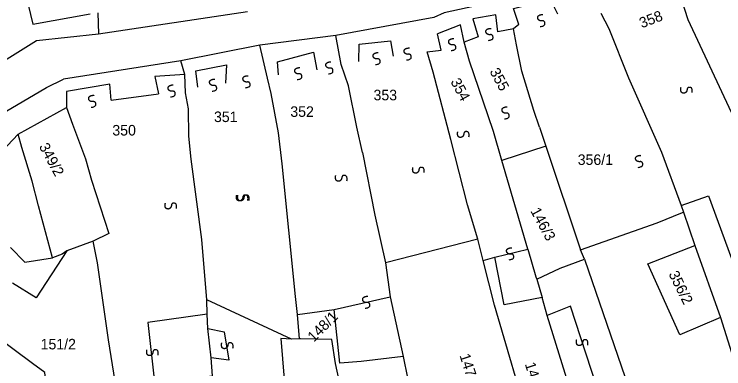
# Model space of a CAD drawing. Extents: x -581999 to -572728, y -1219553 to -1212032.
# Drawn here: x -577714.8 to -577580.3, y -1215727.3 to -1215660.1 of the extents above; entities that cross this region are included whole.
import ezdxf

# ---------------------------------------------------------------- set-up
doc = ezdxf.new("R2010")
doc.units = 0
for name, color, linetype in [('Vrstva 1', 7, 'Continuous'), ('Vrstva 2', 7, 'Continuous'), ('Vrstva 4', 7, 'Continuous'), ('Vrstva 6', 7, 'Continuous')]:
    doc.layers.add(name, color=color, linetype=linetype)

msp = doc.modelspace()

# ---------------------------------------------------------------- linework, layer by layer
at = {"layer": 'Vrstva 1'}
msp.add_line((-577682.456, -1215671.509), (-577683.252, -1215668.949), dxfattribs=at)
for points in [[(-577702.715, -1215611.05), (-577707.55, -1215614.997), (-577714.464, -1215648.832), (-577711.301, -1215661.986), (-577700.407, -1215660.043)], [(-577613.694, -1215654.996), (-577622.577, -1215657.523), (-577633.304, -1215659.812), (-577635.267, -1215660.737)], [(-577619.14, -1215662.069), (-577620.164, -1215659.043), (-577613.242, -1215657.206), (-577611.814, -1215660.001)], [(-577588.315, -1215657.32), (-577587.122, -1215661.102)], [(-577698.978, -1215659.866), (-577698.815, -1215663.828)], [(-577698.815, -1215663.828), (-577670.605, -1215659.602)], [(-577623.179, -1215663.45), (-577623.51, -1215660.194), (-577627.893, -1215660.993), (-577626.87, -1215664.369)], [(-577603.632, -1215659.936), (-577602.104, -1215662.83)], [(-577635.267, -1215660.737), (-577653.837, -1215664.163)], [(-577587.122, -1215661.102), (-577578.944, -1215678.684)], [(-577629.525, -1215665.406), (-577630.202, -1215662.148), (-577634.588, -1215663.82)], [(-577620.181, -1215662.879), (-577623.179, -1215663.45)], [(-577619.14, -1215662.069), (-577620.181, -1215662.879)], [(-577619.618, -1215665.903), (-577620.181, -1215662.879)], [(-577602.104, -1215662.83), (-577598.401, -1215672.177)], [(-577735.744, -1215682.066), (-577719.727, -1215670.767), (-577710.564, -1215665.069), (-577698.815, -1215663.828)], [(-577653.837, -1215664.163), (-577668.253, -1215665.975)], [(-577652.823, -1215669.63), (-577653.837, -1215664.163)], [(-577633.91, -1215666.902), (-577634.588, -1215663.82)], [(-577626.87, -1215664.369), (-577629.525, -1215665.406)], [(-577628.503, -1215669.013), (-577629.525, -1215665.406)], [(-577668.253, -1215665.975), (-577683.252, -1215668.949)], [(-577666.78, -1215672.259), (-577668.253, -1215665.975)], [(-577636.562, -1215667.242), (-577633.91, -1215666.902)], [(-577616.33, -1215678.352), (-577618.617, -1215670.901), (-577619.618, -1215665.903)], [(-577635.426, -1215671.083), (-577636.562, -1215667.242)], [(-577683.252, -1215668.949), (-577705.448, -1215672.439)], [(-577651.456, -1215673.704), (-577652.823, -1215669.63)], [(-577624.975, -1215679.37), (-577628.503, -1215669.013)], [(-577682.456, -1215671.509), (-577688.15, -1215671.915), (-577687.471, -1215675.173)], [(-577682.354, -1215674.998), (-577682.456, -1215671.509)], [(-577666.101, -1215675.167), (-577666.78, -1215672.259)], [(-577632.068, -1215683.842), (-577635.426, -1215671.083)], [(-577598.401, -1215672.177), (-577592.109, -1215686.233), (-577588.384, -1215696.39)], [(-577708.727, -1215673.992), (-577705.448, -1215672.439)], [(-577696.469, -1215676.423), (-577696.688, -1215673.398), (-577704.88, -1215674.767), (-577704.911, -1215677.765)], [(-577649.875, -1215681.498), (-577651.456, -1215673.704)], [(-577914.873, -1215726.747), (-577886.58, -1215723.734), (-577884.746, -1215723.515), (-577875.236, -1215722.423), (-577874.505, -1215722.12), (-577863.622, -1215720.85), (-577862.999, -1215720.979), (-577844.985, -1215718.754), (-577796.098, -1215711.415), (-577783.814, -1215709.901), (-577749.511, -1215702.562), (-577738.438, -1215696.009), (-577724.392, -1215683.952), (-577717.64, -1215679.235), (-577708.727, -1215673.992)], [(-577681.79, -1215678.023), (-577682.354, -1215674.998)], [(-577696.469, -1215676.423), (-577687.471, -1215675.173)], [(-577664.747, -1215682.612), (-577666.101, -1215675.167)], [(-577714.064, -1215682.842), (-577704.911, -1215677.765)], [(-577704.911, -1215677.765), (-577703.747, -1215680.96)], [(-577681.695, -1215683.255), (-577681.79, -1215678.023)], [(-577615.266, -1215681.526), (-577616.33, -1215678.352)], [(-577623.944, -1215682.319), (-577624.975, -1215679.37)], [(-577703.747, -1215680.96), (-577701.33, -1215687.533)], [(-577648.777, -1215686.329), (-577649.875, -1215681.498)], [(-577615.266, -1215681.526), (-577614.055, -1215685.1)], [(-577714.064, -1215682.842), (-577722.147, -1215691.388), (-577724.874, -1215694.936)], [(-577713.351, -1215685.398), (-577714.064, -1215682.842)], [(-577664.041, -1215688.467), (-577664.747, -1215682.612)], [(-577622.362, -1215687.863), (-577623.944, -1215682.319)], [(-577681.299, -1215687.604), (-577681.695, -1215683.255)], [(-577628.867, -1215696.25), (-577632.068, -1215683.842)], [(-577711.386, -1215691.788), (-577713.351, -1215685.398)], [(-577614.055, -1215685.1), (-577622.362, -1215687.863)], [(-577614.055, -1215685.1), (-577607.507, -1215704.793)], [(-577648.777, -1215686.329), (-577646.477, -1215698.187)], [(-577701.33, -1215687.533), (-577700.171, -1215691.55)], [(-577679.283, -1215702.801), (-577681.299, -1215687.604)], [(-577661.522, -1215713.635), (-577664.041, -1215688.467)], [(-577617.445, -1215704.636), (-577622.362, -1215687.863)], [(-577710.228, -1215696.442), (-577711.386, -1215691.788)], [(-577700.171, -1215691.55), (-577696.865, -1215701.681), (-577699.854, -1215703.131)], [(-577588.384, -1215696.39), (-577583.201, -1215694.517)], [(-577583.201, -1215694.517), (-577572.653, -1215723.27)], [(-577707.553, -1215706.298), (-577710.228, -1215696.442)], [(-577626.921, -1215702.783), (-577628.867, -1215696.25)], [(-577588.384, -1215696.39), (-577587.93, -1215697.611)], [(-577592.941, -1215699.643), (-577588.119, -1215697.693), (-577587.93, -1215697.611)], [(-577587.93, -1215697.611), (-577585.804, -1215703.949)], [(-577646.477, -1215698.187), (-577644.436, -1215707.218)], [(-577607.507, -1215704.793), (-577592.941, -1215699.643)], [(-577699.854, -1215703.131), (-577704.835, -1215704.939)], [(-577693.061, -1215745.931), (-577696.944, -1215721.858), (-577699.052, -1215707.217), (-577699.854, -1215703.131)], [(-577678.335, -1215714.289), (-577679.283, -1215702.801)], [(-577626.921, -1215702.783), (-577644.436, -1215707.218)], [(-577625.945, -1215706.796), (-577626.921, -1215702.783)], [(-577715.504, -1215704.359), (-577712.801, -1215707.103), (-577707.553, -1215706.298)], [(-577617.445, -1215704.636), (-577615.932, -1215709.927), (-577615.759, -1215710.366)], [(-577580.965, -1215717.624), (-577588.68, -1215720.898), (-577594.688, -1215707.455), (-577585.804, -1215703.949)], [(-577585.804, -1215703.949), (-577580.965, -1215717.624)], [(-577704.835, -1215704.939), (-577710.656, -1215713.856), (-577715.168, -1215711.106)], [(-577704.835, -1215704.939), (-577705.741, -1215705.574), (-577707.553, -1215706.298)], [(-577606.708, -1215706.567), (-577607.507, -1215704.793)], [(-577644.436, -1215707.218), (-577643.56, -1215713.691)], [(-577625.945, -1215706.796), (-577623.686, -1215706.166)], [(-577616.887, -1215738.765), (-577623.812, -1215715.278), (-577625.945, -1215706.796)], [(-577614.775, -1215713.849), (-577621.917, -1215715.194), (-577623.686, -1215706.166)], [(-577615.759, -1215710.366), (-577611.324, -1215708.284), (-577606.708, -1215706.567)], [(-577606.708, -1215706.567), (-577599.039, -1215729.005)], [(-577615.759, -1215710.366), (-577614.775, -1215713.849)], [(-577661.091, -1215717.068), (-577661.522, -1215713.635)], [(-577643.56, -1215713.691), (-577641.076, -1215724.999)], [(-577613.801, -1215717.207), (-577614.775, -1215713.849)], [(-577678.212, -1215717.002), (-577678.335, -1215714.289)], [(-577662.285, -1215721.712), (-577678.335, -1215714.289)], [(-577661.091, -1215717.068), (-577654.164, -1215716.124)], [(-577653.079, -1215726.283), (-577654.164, -1215716.124)], [(-577678.09, -1215719.715), (-577678.212, -1215717.002)], [(-577660.748, -1215721.626), (-577661.091, -1215717.068)], [(-577607.744, -1215736.632), (-577609.259, -1215731.89), (-577613.801, -1215717.207)], [(-577580.965, -1215717.624), (-577574.064, -1215739.543)], [(-577711.336, -1215726.312), (-577721.347, -1215718.929)], [(-577677.479, -1215725.277), (-577678.09, -1215719.715)], [(-577662.285, -1215721.712), (-577664.284, -1215721.582), (-577662.648, -1215741.635)], [(-577660.748, -1215721.626), (-577662.285, -1215721.712)], [(-577653.297, -1215729.272), (-577653.909, -1215726.352), (-577654.614, -1215721.793), (-577660.578, -1215721.683), (-577660.748, -1215721.626)], [(-577677.221, -1215728.649), (-577677.479, -1215725.277)], [(-577641.076, -1215724.999), (-577649.031, -1215725.94), (-577653.079, -1215726.283)], [(-577641.076, -1215724.999), (-577640.284, -1215729.038)], [(-577708.642, -1215731.424), (-577708.992, -1215728.051), (-577711.336, -1215726.312)]]:
    msp.add_lwpolyline(points, dxfattribs=at)
at = {"layer": 'Vrstva 4'}
for p, q in [((-577609.361, -1215715.461), (-577613.801, -1215717.207)), ((-577604.345, -1215730.793), (-577609.361, -1215715.461))]:
    msp.add_line(p, q, dxfattribs=at)
for points in [[(-577649.477, -1215669.061), (-577649.464, -1215665.805), (-577643.468, -1215665.127), (-577643.019, -1215668.035)], [(-577664.702, -1215671.568), (-577664.923, -1215669.125), (-577658.115, -1215667.288), (-577657.437, -1215670.661)], [(-577680.044, -1215673.959), (-577680.377, -1215670.819), (-577674.609, -1215669.675), (-577674.737, -1215673.163)], [(-577623.686, -1215706.166), (-577617.445, -1215704.636)], [(-577654.164, -1215716.124), (-577643.56, -1215713.691)], [(-577678.212, -1215717.002), (-577689.475, -1215718.553), (-577688.254, -1215729.86), (-577677.221, -1215728.649)], [(-577678.09, -1215719.715), (-577675.024, -1215720.306), (-577674.142, -1215725.687), (-577677.479, -1215725.277)]]:
    msp.add_lwpolyline(points, dxfattribs=at)
at = {"layer": 'Vrstva 6'}
for points in [[(-577615.117, -1215662.436), (-577614.266, -1215662.347), (-577614.214, -1215661.589), (-577614.53, -1215661.333), (-577614.946, -1215661.378), (-577615.278, -1215661.296), (-577615.495, -1215661.088), (-577615.586, -1215660.876), (-577615.587, -1215660.607), (-577615.384, -1215660.302), (-577614.796, -1215660.132), (-577614.616, -1215660.165)], [(-577624.938, -1215665.063), (-577624.087, -1215664.974), (-577624.035, -1215664.216), (-577624.351, -1215663.96), (-577624.767, -1215664.005), (-577625.099, -1215663.923), (-577625.316, -1215663.715), (-577625.407, -1215663.503), (-577625.408, -1215663.234), (-577625.205, -1215662.929), (-577624.617, -1215662.759), (-577624.437, -1215662.792)], [(-577631.998, -1215667.002), (-577631.147, -1215666.913), (-577631.095, -1215666.155), (-577631.411, -1215665.899), (-577631.827, -1215665.944), (-577632.159, -1215665.862), (-577632.376, -1215665.654), (-577632.467, -1215665.442), (-577632.468, -1215665.173), (-577632.265, -1215664.868), (-577631.677, -1215664.698), (-577631.497, -1215664.731)], [(-577640.433, -1215668.785), (-577639.582, -1215668.696), (-577639.53, -1215667.938), (-577639.846, -1215667.682), (-577640.262, -1215667.727), (-577640.594, -1215667.645), (-577640.811, -1215667.437), (-577640.902, -1215667.225), (-577640.903, -1215666.956), (-577640.7, -1215666.651), (-577640.112, -1215666.481), (-577639.932, -1215666.514)], [(-577646.326, -1215669.66), (-577645.475, -1215669.571), (-577645.423, -1215668.813), (-577645.739, -1215668.557), (-577646.155, -1215668.602), (-577646.487, -1215668.52), (-577646.704, -1215668.312), (-577646.795, -1215668.1), (-577646.796, -1215667.831), (-577646.593, -1215667.526), (-577646.005, -1215667.356), (-577645.825, -1215667.389)], [(-577655.274, -1215671.411), (-577654.423, -1215671.322), (-577654.371, -1215670.564), (-577654.687, -1215670.308), (-577655.103, -1215670.353), (-577655.435, -1215670.271), (-577655.652, -1215670.063), (-577655.743, -1215669.851), (-577655.744, -1215669.582), (-577655.541, -1215669.277), (-577654.953, -1215669.107), (-577654.773, -1215669.14)], [(-577661.167, -1215672.506), (-577660.316, -1215672.417), (-577660.264, -1215671.659), (-577660.58, -1215671.403), (-577660.996, -1215671.448), (-577661.328, -1215671.366), (-577661.545, -1215671.158), (-577661.636, -1215670.946), (-577661.637, -1215670.677), (-577661.434, -1215670.372), (-577660.846, -1215670.202), (-577660.666, -1215670.235)], [(-577670.988, -1215674.038), (-577670.137, -1215673.949), (-577670.085, -1215673.191), (-577670.401, -1215672.935), (-577670.817, -1215672.98), (-577671.149, -1215672.898), (-577671.366, -1215672.69), (-577671.457, -1215672.478), (-577671.458, -1215672.209), (-577671.255, -1215671.904), (-577670.667, -1215671.734), (-577670.487, -1215671.767)], [(-577685.174, -1215675.789), (-577684.323, -1215675.7), (-577684.271, -1215674.942), (-577684.587, -1215674.686), (-577685.003, -1215674.731), (-577685.335, -1215674.649), (-577685.552, -1215674.441), (-577685.643, -1215674.229), (-577685.644, -1215673.96), (-577685.441, -1215673.655), (-577684.853, -1215673.485), (-577684.673, -1215673.518)], [(-577677.317, -1215674.695), (-577676.466, -1215674.606), (-577676.414, -1215673.848), (-577676.73, -1215673.592), (-577677.146, -1215673.637), (-577677.478, -1215673.555), (-577677.695, -1215673.347), (-577677.786, -1215673.135), (-577677.787, -1215672.866), (-577677.584, -1215672.561), (-577676.996, -1215672.391), (-577676.816, -1215672.424)], [(-577586.307, -1215674.972), (-577586.212, -1215674.121), (-577586.942, -1215673.909), (-577587.259, -1215674.163), (-577587.304, -1215674.579), (-577587.455, -1215674.886), (-577587.704, -1215675.053), (-577587.931, -1215675.097), (-577588.194, -1215675.041), (-577588.449, -1215674.777), (-577588.489, -1215674.167), (-577588.419, -1215673.998)], [(-577700.233, -1215677.759), (-577699.382, -1215677.67), (-577699.33, -1215676.912), (-577699.646, -1215676.656), (-577700.062, -1215676.701), (-577700.394, -1215676.619), (-577700.611, -1215676.411), (-577700.702, -1215676.199), (-577700.703, -1215675.93), (-577700.5, -1215675.625), (-577699.912, -1215675.455), (-577699.732, -1215675.488)], [(-577621.883, -1215679.948), (-577621.032, -1215679.859), (-577620.98, -1215679.101), (-577621.296, -1215678.845), (-577621.712, -1215678.89), (-577622.044, -1215678.808), (-577622.261, -1215678.6), (-577622.352, -1215678.388), (-577622.353, -1215678.119), (-577622.15, -1215677.814), (-577621.562, -1215677.644), (-577621.382, -1215677.677)], [(-577628.615, -1215683.357), (-577628.52, -1215682.506), (-577629.25, -1215682.294), (-577629.567, -1215682.548), (-577629.612, -1215682.964), (-577629.763, -1215683.271), (-577630.012, -1215683.438), (-577630.239, -1215683.482), (-577630.502, -1215683.426), (-577630.757, -1215683.162), (-577630.797, -1215682.552), (-577630.727, -1215682.383)], [(-577596.566, -1215689.142), (-577595.715, -1215689.053), (-577595.663, -1215688.295), (-577595.979, -1215688.039), (-577596.395, -1215688.084), (-577596.727, -1215688.002), (-577596.944, -1215687.794), (-577597.035, -1215687.582), (-577597.036, -1215687.313), (-577596.833, -1215687.008), (-577596.245, -1215686.838), (-577596.065, -1215686.871)], [(-577637.127, -1215690.143), (-577637.032, -1215689.292), (-577637.762, -1215689.08), (-577638.079, -1215689.334), (-577638.124, -1215689.75), (-577638.275, -1215690.057), (-577638.524, -1215690.224), (-577638.751, -1215690.268), (-577639.014, -1215690.212), (-577639.269, -1215689.948), (-577639.309, -1215689.338), (-577639.239, -1215689.169)], [(-577651.749, -1215691.675), (-577651.654, -1215690.824), (-577652.384, -1215690.612), (-577652.701, -1215690.866), (-577652.746, -1215691.282), (-577652.897, -1215691.589), (-577653.146, -1215691.756), (-577653.373, -1215691.8), (-577653.636, -1215691.744), (-577653.891, -1215691.48), (-577653.931, -1215690.87), (-577653.861, -1215690.701)], [(-577670.518, -1215695.397), (-577670.423, -1215694.546), (-577671.153, -1215694.334), (-577671.47, -1215694.588), (-577671.515, -1215695.004), (-577671.666, -1215695.311), (-577671.915, -1215695.478), (-577672.142, -1215695.522), (-577672.405, -1215695.466), (-577672.66, -1215695.202), (-577672.7, -1215694.592), (-577672.63, -1215694.423)], [(-577670.3, -1215695.397), (-577670.205, -1215694.546), (-577670.935, -1215694.334), (-577671.252, -1215694.588), (-577671.297, -1215695.004), (-577671.448, -1215695.311), (-577671.697, -1215695.478), (-577671.924, -1215695.522), (-577672.187, -1215695.466), (-577672.442, -1215695.202), (-577672.482, -1215694.592), (-577672.412, -1215694.423)], [(-577684.049, -1215696.929), (-577683.954, -1215696.078), (-577684.684, -1215695.866), (-577685.001, -1215696.12), (-577685.046, -1215696.536), (-577685.197, -1215696.843), (-577685.446, -1215697.01), (-577685.673, -1215697.054), (-577685.936, -1215696.998), (-577686.191, -1215696.734), (-577686.231, -1215696.124), (-577686.161, -1215695.955)], [(-577621.019, -1215706.668), (-577620.168, -1215706.579), (-577620.116, -1215705.821), (-577620.432, -1215705.565), (-577620.848, -1215705.61), (-577621.18, -1215705.528), (-577621.397, -1215705.32), (-577621.488, -1215705.108), (-577621.489, -1215704.839), (-577621.286, -1215704.534), (-577620.698, -1215704.364), (-577620.518, -1215704.397)], [(-577648.299, -1215715.862), (-577647.448, -1215715.773), (-577647.396, -1215715.015), (-577647.712, -1215714.759), (-577648.128, -1215714.804), (-577648.46, -1215714.722), (-577648.677, -1215714.514), (-577648.768, -1215714.302), (-577648.769, -1215714.033), (-577648.566, -1215713.728), (-577647.978, -1215713.558), (-577647.798, -1215713.591)], [(-577606.092, -1215722.832), (-577605.997, -1215721.981), (-577606.727, -1215721.769), (-577607.044, -1215722.023), (-577607.089, -1215722.439), (-577607.24, -1215722.746), (-577607.489, -1215722.913), (-577607.716, -1215722.957), (-577607.979, -1215722.901), (-577608.234, -1215722.637), (-577608.274, -1215722.027), (-577608.204, -1215721.858)], [(-577673.356, -1215723.416), (-577673.261, -1215722.565), (-577673.991, -1215722.353), (-577674.308, -1215722.607), (-577674.353, -1215723.023), (-577674.504, -1215723.33), (-577674.753, -1215723.497), (-577674.98, -1215723.541), (-577675.243, -1215723.485), (-577675.498, -1215723.221), (-577675.538, -1215722.611), (-577675.468, -1215722.442)], [(-577687.542, -1215724.729), (-577687.447, -1215723.878), (-577688.177, -1215723.666), (-577688.494, -1215723.92), (-577688.539, -1215724.336), (-577688.69, -1215724.643), (-577688.939, -1215724.81), (-577689.166, -1215724.854), (-577689.429, -1215724.798), (-577689.684, -1215724.534), (-577689.724, -1215723.924), (-577689.654, -1215723.755)]]:
    msp.add_open_spline(points, degree=2, dxfattribs=at)

# ---------------------------------------------------------------- texts
at = {"layer": 'Vrstva 2'}
for s, rotation, p in [('358', 21.05858, (-577595.869, -1215662.791)), ('355', 298.36948, (-577624.768, -1215670.942)), ('354', 298.36948, (-577632.178, -1215672.88)), ('349/2', 298.36948, (-577710.181, -1215685.171)), ('146/3', 298.36948, (-577617.026, -1215697.404)), ('356/2', 296.37269, (-577590.837, -1215709.354)), ('148/1', 45.13614, (-577658.027, -1215722.38)), ('147/1', 287.74102, (-577630.43, -1215724.806)), ('146/2', 287.74102, (-577618.052, -1215726.434))]:
    msp.add_text(s, height=2, rotation=rotation, dxfattribs=at).set_placement(p)
for s, p in [('353', (-577646.709, -1215676.428)), ('352', (-577662.483, -1215679.57)), ('351', (-577676.951, -1215680.552)), ('350', (-577696.217, -1215683.105)), ('356/1', (-577608.009, -1215688.68)), ('151/2', (-577709.808, -1215723.661))]:
    msp.add_text(s, height=2, dxfattribs=at).set_placement(p)

doc.saveas('drawing.dxf')
